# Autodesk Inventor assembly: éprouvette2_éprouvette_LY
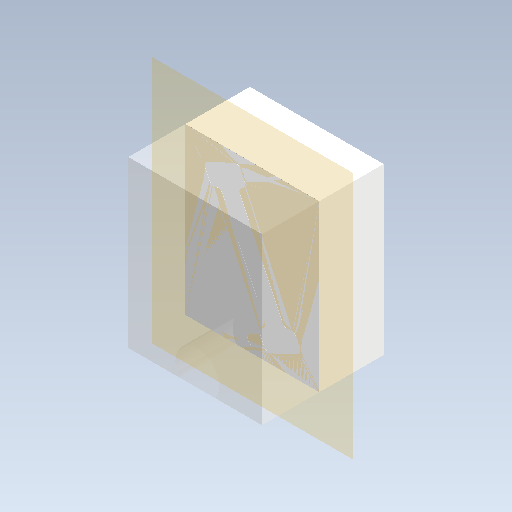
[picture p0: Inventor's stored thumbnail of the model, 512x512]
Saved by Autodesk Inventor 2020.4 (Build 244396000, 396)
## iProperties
Created: 2021-10
Part Number: éprouvette2_éprouvette_LY
Document SubType Name: Assembly
Designer: mel
Author: mel
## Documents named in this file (2)
- D:\travail\année 2020-2021\itec\prépa injection plastique eduscol\dossier de travail\Ensemble des pièces de l'activité\Conception de moule1\éprouvette2_éprouvette_LY.iam
- D:\travail\année 2020-2021\itec\prépa injection plastique eduscol\dossier de travail\Ensemble des pièces de l'activité\Conception de moule1\éprouvette2_éprouvette_PZ.iam
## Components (1 placed, 1 different names)
1. éprouvette2_éprouvette_PZ:1 [sub-assembly] — Affleurement:1, Affleurement:2, Affleurement:3
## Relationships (3: Flush 3)
- Affleurement:1 [Flush]: éprouvette2_éprouvette_PZ:1
- Affleurement:2 [Flush]: éprouvette2_éprouvette_PZ:1
- Affleurement:3 [Flush]: éprouvette2_éprouvette_PZ:1
